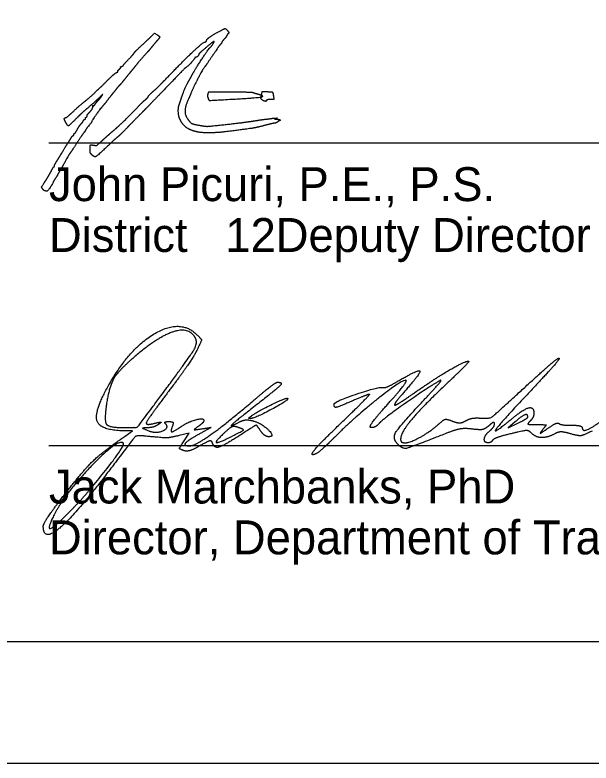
# Model space of a CAD drawing. Extents: x 0 to 96.2, y -27.5 to 31.3.
# Drawn here: x 69.212 to 71.59, y -0.113 to 2.975 of the extents above; entities that cross this region are included whole.
import ezdxf

# ---------------------------------------------------------------- set-up
doc = ezdxf.new("R2010")
doc.units = 0
for name, color, linetype in [('DIM', 7, 'Continuous'), ('TB1', 7, 'Continuous'), ('TB_SUPER_50x1', 7, 'Continuous'), ('text', 7, 'Continuous')]:
    doc.layers.add(name, color=color, linetype=linetype)

msp = doc.modelspace()

# ---------------------------------------------------------------- linework, layer by layer
at = {"layer": 'DIM'}
msp.add_lwpolyline([(43.2234, 21.3869), (74.7234, 21.3869), (74.7234, 0.3869), (43.2234, 0.3869)], close=True, dxfattribs=at)
at = {"layer": 'TB1'}
for p, q in [((69.352, 2.4468), (72.852, 2.4468)), ((69.352, 1.1985), (72.852, 1.1985))]:
    msp.add_line(p, q, dxfattribs=at)
at = {"layer": 'TB_SUPER_50x1'}
for p, q in [((70.0084, 2.6328), (70.0084, 2.6328)), ((70.2313, 2.6259), (70.2313, 2.6259)), ((69.5269, 2.4004), (69.5269, 2.4004)), ((69.336, 2.2489), (69.336, 2.2489)), ((69.8143, 1.4035), (69.8143, 1.4035)), ((70.1796, 1.3137), (70.1796, 1.3137)), ((71.3286, 1.3157), (71.3286, 1.3157)), ((70.1348, 1.272), (70.1348, 1.272)), ((70.5514, 1.2847), (70.5514, 1.2847))]:
    msp.add_line(p, q, dxfattribs=at)
for points in [[(69.7768, 2.8893), (69.7877, 2.9), (69.7973, 2.8942)], [(70.1011, 2.6567), (70.0105, 2.6572), (70.0078, 2.6492)], [(70.2529, 2.6574), (70.2311, 2.6579), (70.2282, 2.6442)], [(69.5708, 2.6419), (69.5742, 2.6483), (69.5678, 2.6419)], [(70.2666, 2.6275), (70.2814, 2.6275), (70.2797, 2.6406)], [(71.2768, 1.296), (71.2473, 1.2704), (71.288, 1.2901)], [(69.6666, 1.2366), (69.6973, 1.2578), (69.6595, 1.2585)], [(69.9096, 1.2167), (69.9308, 1.2491), (69.8891, 1.239)]]:
    msp.add_lwpolyline(points, dxfattribs=at)
for points in [[(70.0022, 2.8688), (70.0022, 2.874), (70.0282, 2.8932), (70.0543, 2.9072)], [(70.0543, 2.9072), (70.0769, 2.9192), (70.082, 2.9193), (70.0917, 2.9076)], [(70.0917, 2.9076), (70.0952, 2.9034), (70.095, 2.9016), (70.0906, 2.8968)], [(69.7353, 2.8501), (69.7522, 2.8659), (69.7709, 2.8835), (69.7768, 2.8893)], [(69.7973, 2.8942), (69.8089, 2.8874), (69.8095, 2.8814), (69.7997, 2.8707)], [(70.0758, 2.8761), (70.0705, 2.8705), (70.0662, 2.8647), (70.0662, 2.8633)], [(70.0854, 2.8887), (70.0854, 2.8874), (70.0811, 2.8818), (70.0758, 2.8761)], [(70.0906, 2.8968), (70.0877, 2.8936), (70.0854, 2.89), (70.0854, 2.8887)], [(69.7046, 2.8194), (69.7046, 2.8206), (69.7184, 2.8344), (69.7353, 2.8501)], [(69.7797, 2.8469), (69.7727, 2.8381), (69.7648, 2.8287), (69.7622, 2.8259)], [(69.7997, 2.8707), (69.7957, 2.8663), (69.7867, 2.8556), (69.7797, 2.8469)], [(69.8229, 2.699), (69.8932, 2.7726), (69.9852, 2.8608), (69.994, 2.863)], [(70.0342, 2.8657), (70.0342, 2.8679), (70.0091, 2.8485), (69.9857, 2.8281)], [(69.994, 2.863), (69.9985, 2.8641), (70.0022, 2.8667), (70.0022, 2.8688)], [(70.0167, 2.8403), (70.0213, 2.8444), (70.0342, 2.863), (70.0342, 2.8657)], [(70.0622, 2.8562), (70.0541, 2.8472), (70.0509, 2.8427), (70.0245, 2.8035)], [(70.0662, 2.8633), (70.0662, 2.8618), (70.0644, 2.8587), (70.0622, 2.8562)], [(69.6822, 2.7939), (69.6945, 2.8068), (69.7046, 2.8183), (69.7046, 2.8194)], [(69.7622, 2.8259), (69.7508, 2.8138), (69.72, 2.7784), (69.7093, 2.7651)], [(69.9429, 2.7278), (69.9548, 2.7501), (70.0102, 2.8346), (70.0167, 2.8403)], [(69.9702, 2.8121), (69.9702, 2.8083), (69.9616, 2.8003), (69.9576, 2.8003)], [(69.9857, 2.8281), (69.9772, 2.8207), (69.9702, 2.8135), (69.9702, 2.8121)], [(69.6598, 2.768), (69.6598, 2.7694), (69.6699, 2.781), (69.6822, 2.7939)], [(69.9541, 2.7979), (69.954, 2.795), (69.9209, 2.7587), (69.9184, 2.7587)], [(69.9576, 2.8003), (69.9557, 2.8003), (69.9541, 2.7992), (69.9541, 2.7979)], [(70.0245, 2.8035), (70.0096, 2.7815), (69.9968, 2.7628), (69.9958, 2.7619)], [(69.6361, 2.7419), (69.6351, 2.7429), (69.6378, 2.7469), (69.642, 2.7509)], [(69.642, 2.7509), (69.6463, 2.7548), (69.649, 2.7588), (69.6481, 2.7597)], [(69.6481, 2.7597), (69.6472, 2.7606), (69.6495, 2.7623), (69.6531, 2.7634)], [(69.6531, 2.7634), (69.6568, 2.7646), (69.6598, 2.7667), (69.6598, 2.768)], [(69.7093, 2.7651), (69.7028, 2.7572), (69.6929, 2.745), (69.6871, 2.7379)], [(69.9184, 2.7587), (69.9164, 2.7587), (69.8857, 2.7276), (69.816, 2.6549)], [(69.9958, 2.7619), (69.989, 2.7554), (69.9494, 2.6795), (69.9366, 2.6483)], [(69.5949, 2.7066), (69.6114, 2.7228), (69.6279, 2.7369), (69.6314, 2.7381)], [(69.6314, 2.7381), (69.635, 2.7392), (69.637, 2.7409), (69.6361, 2.7419)], [(69.6871, 2.7379), (69.6814, 2.7309), (69.6697, 2.7165), (69.6612, 2.7059)], [(69.9283, 2.7011), (69.9299, 2.7038), (69.9365, 2.7158), (69.9429, 2.7278)], [(69.5023, 2.6204), (69.5197, 2.6346), (69.5537, 2.6662), (69.5949, 2.7066)], [(69.6612, 2.7059), (69.6527, 2.6954), (69.6441, 2.6853), (69.6421, 2.6835)], [(69.7821, 2.6596), (69.793, 2.6692), (69.8114, 2.687), (69.8229, 2.699)], [(69.8982, 2.6307), (69.9031, 2.6471), (69.9216, 2.6901), (69.9283, 2.7011)], [(69.6259, 2.6643), (69.619, 2.6555), (69.6126, 2.6476), (69.6116, 2.6467)], [(69.6421, 2.6835), (69.6401, 2.6818), (69.6328, 2.6731), (69.6259, 2.6643)], [(69.7622, 2.6387), (69.7622, 2.6405), (69.7711, 2.6499), (69.7821, 2.6596)], [(70.1954, 2.6539), (70.1934, 2.6551), (70.151, 2.6564), (70.1011, 2.6567)], [(70.2763, 2.6553), (70.2754, 2.6562), (70.2649, 2.6571), (70.2529, 2.6574)], [(69.5678, 2.6419), (69.556, 2.63), (69.5335, 2.6096), (69.5094, 2.5891)], [(69.5431, 2.6075), (69.5463, 2.6124), (69.553, 2.6206), (69.5582, 2.6259)], [(69.5582, 2.6259), (69.5633, 2.6312), (69.569, 2.6384), (69.5708, 2.6419)], [(69.5948, 2.6253), (69.5865, 2.6144), (69.5778, 2.6036), (69.5755, 2.6013)], [(69.6116, 2.6467), (69.6107, 2.6458), (69.6031, 2.6362), (69.5948, 2.6253)], [(69.7209, 2.5975), (69.7307, 2.6079), (69.7441, 2.6206), (69.7505, 2.6259)], [(69.816, 2.6549), (69.7908, 2.6286), (69.7551, 2.5917), (69.7366, 2.573)], [(69.7505, 2.6259), (69.7569, 2.6312), (69.7622, 2.6369), (69.7622, 2.6387)], [(69.8899, 2.6058), (69.8915, 2.6098), (69.8953, 2.621), (69.8982, 2.6307)], [(69.9284, 2.6291), (69.9155, 2.6016), (69.9123, 2.5656), (69.9213, 2.5514)], [(69.9366, 2.6483), (69.9337, 2.6413), (69.93, 2.6326), (69.9284, 2.6291)], [(70.0078, 2.6492), (70.0063, 2.6446), (70.0065, 2.6377), (70.0084, 2.6328)], [(70.0084, 2.6328), (70.0122, 2.6227), (70.0153, 2.6225), (70.1078, 2.6275)], [(70.1078, 2.6275), (70.2094, 2.633), (70.2463, 2.6403), (70.2125, 2.6483)], [(70.2125, 2.6483), (70.2051, 2.6501), (70.1974, 2.6526), (70.1954, 2.6539)], [(70.2282, 2.6442), (70.2256, 2.6324), (70.2261, 2.6299), (70.2313, 2.6259)], [(70.2313, 2.6259), (70.2383, 2.6206), (70.2518, 2.6196), (70.2518, 2.6243)], [(70.2518, 2.6243), (70.2518, 2.6261), (70.2584, 2.6275), (70.2666, 2.6275)], [(70.2797, 2.6406), (70.2787, 2.6478), (70.2772, 2.6544), (70.2763, 2.6553)], [(69.4493, 2.574), (69.4706, 2.5942), (69.4762, 2.5991), (69.5023, 2.6204)], [(69.5135, 2.5673), (69.5251, 2.5792), (69.5353, 2.5956), (69.5332, 2.5991)], [(69.5755, 2.6013), (69.5688, 2.5946), (69.5286, 2.5382), (69.5286, 2.5355)], [(69.5332, 2.5991), (69.5317, 2.6014), (69.5321, 2.6021), (69.5341, 2.6008)], [(69.5341, 2.6008), (69.536, 2.5997), (69.54, 2.6027), (69.5431, 2.6075)], [(69.6366, 2.5139), (69.6493, 2.525), (69.6949, 2.5703), (69.7209, 2.5975)], [(69.8917, 2.5471), (69.8864, 2.5591), (69.8854, 2.5944), (69.8899, 2.6058)], [(69.4224, 2.5521), (69.4256, 2.5532), (69.4377, 2.563), (69.4493, 2.574)], [(69.5094, 2.5891), (69.4962, 2.5779), (69.4773, 2.5606), (69.4675, 2.5507)], [(69.5094, 2.5585), (69.5094, 2.561), (69.5112, 2.565), (69.5135, 2.5673)], [(69.7366, 2.573), (69.7181, 2.5543), (69.6897, 2.5253), (69.6734, 2.5085)], [(69.4215, 2.5314), (69.415, 2.5438), (69.4153, 2.5499), (69.4224, 2.5521)], [(69.4675, 2.5507), (69.4364, 2.5193), (69.4293, 2.5163), (69.4215, 2.5314)], [(69.4848, 2.5258), (69.489, 2.5303), (69.4933, 2.5363), (69.4944, 2.5392)], [(69.4944, 2.5392), (69.4955, 2.542), (69.4979, 2.5443), (69.4997, 2.5443)], [(69.4997, 2.5443), (69.5015, 2.5443), (69.503, 2.5465), (69.503, 2.5491)], [(69.503, 2.5491), (69.503, 2.5518), (69.5044, 2.5539), (69.5062, 2.5539)], [(69.5062, 2.5539), (69.5079, 2.5539), (69.5094, 2.556), (69.5094, 2.5585)], [(69.5286, 2.5355), (69.5286, 2.5335), (69.5252, 2.5289), (69.5099, 2.5105)], [(69.954, 2.495), (69.9283, 2.5026), (69.9012, 2.5252), (69.8917, 2.5471)], [(69.9213, 2.5514), (69.9341, 2.5314), (69.9474, 2.524), (69.98, 2.5186)], [(70.0678, 2.5216), (70.1238, 2.5278), (70.1738, 2.5341), (70.2054, 2.5391)], [(70.2054, 2.5391), (70.2182, 2.5412), (70.2482, 2.5452), (70.2582, 2.5462)], [(70.2582, 2.5462), (70.2626, 2.5466), (70.2662, 2.5472), (70.2662, 2.5475)], [(70.2662, 2.5475), (70.2662, 2.5478), (70.2734, 2.5486), (70.2822, 2.5492)], [(70.2822, 2.5492), (70.2939, 2.5501), (70.296, 2.5496), (70.2902, 2.5477)], [(70.2945, 2.5331), (70.2919, 2.5305), (70.2866, 2.5283), (70.2827, 2.5282)], [(70.2902, 2.5477), (70.2829, 2.5452), (70.2833, 2.5449), (70.2942, 2.5446)], [(70.2942, 2.5446), (70.3008, 2.5445), (70.3062, 2.5429), (70.3062, 2.5411)], [(70.3027, 2.5379), (70.3009, 2.5379), (70.2972, 2.5358), (70.2945, 2.5331)], [(70.3062, 2.5411), (70.3062, 2.5394), (70.3046, 2.5379), (70.3027, 2.5379)], [(69.4577, 2.4867), (69.4591, 2.4867), (69.4641, 2.4936), (69.4687, 2.5021)], [(69.4687, 2.5021), (69.4733, 2.5106), (69.4806, 2.5212), (69.4848, 2.5258)], [(69.5099, 2.5105), (69.5083, 2.5086), (69.5052, 2.5036), (69.5029, 2.4993)], [(69.6067, 2.4879), (69.6171, 2.4969), (69.6306, 2.5086), (69.6366, 2.5139)], [(69.6734, 2.5085), (69.6572, 2.4917), (69.6394, 2.4745), (69.6341, 2.4703)], [(69.98, 2.5186), (70.0007, 2.5152), (70.0121, 2.5156), (70.0678, 2.5216)], [(70.2518, 2.5216), (70.2141, 2.5113), (70.1749, 2.5048), (70.0806, 2.4931)], [(70.2827, 2.5282), (70.2789, 2.5282), (70.265, 2.5252), (70.2518, 2.5216)], [(69.4447, 2.4696), (69.447, 2.4737), (69.4503, 2.4771), (69.4519, 2.4771)], [(69.4519, 2.4771), (69.4536, 2.4771), (69.455, 2.4793), (69.455, 2.4819)], [(69.455, 2.4819), (69.455, 2.4846), (69.4562, 2.4867), (69.4577, 2.4867)], [(69.4967, 2.4899), (69.4955, 2.489), (69.4827, 2.4703), (69.4683, 2.4483)], [(69.5029, 2.4993), (69.5007, 2.495), (69.4979, 2.4908), (69.4967, 2.4899)], [(69.5686, 2.4536), (69.5791, 2.4634), (69.5963, 2.4789), (69.6067, 2.4879)], [(70.0806, 2.4931), (70.0398, 2.4881), (69.9742, 2.4891), (69.954, 2.495)], [(69.4003, 2.3974), (69.4174, 2.4261), (69.4251, 2.4386), (69.4323, 2.4496)], [(69.4323, 2.4496), (69.4369, 2.4564), (69.4425, 2.4654), (69.4447, 2.4696)], [(69.4683, 2.4483), (69.4538, 2.4263), (69.4408, 2.4068), (69.4393, 2.4049)], [(69.6012, 2.4406), (69.5536, 2.3948), (69.5391, 2.3869), (69.5269, 2.4004)], [(69.5378, 2.4376), (69.5485, 2.4358), (69.5509, 2.4371), (69.5686, 2.4536)], [(69.6341, 2.4703), (69.6287, 2.4661), (69.6139, 2.4528), (69.6012, 2.4406)], [(69.5269, 2.4004), (69.5231, 2.4046), (69.5213, 2.4111), (69.5216, 2.4198)], [(69.5216, 2.4198), (69.5223, 2.4376), (69.5243, 2.4397), (69.5378, 2.4376)], [(69.3854, 2.3735), (69.3911, 2.3824), (69.3978, 2.3932), (69.4003, 2.3974)], [(69.4393, 2.4049), (69.4368, 2.4018), (69.4326, 2.3944), (69.4113, 2.3563)], [(69.36, 2.3283), (69.3654, 2.3389), (69.371, 2.348), (69.3724, 2.3486)], [(69.3724, 2.3486), (69.3738, 2.3492), (69.375, 2.3514), (69.375, 2.3535)], [(69.375, 2.3535), (69.375, 2.3556), (69.3797, 2.3646), (69.3854, 2.3735)], [(69.4113, 2.3563), (69.4066, 2.348), (69.3994, 2.3357), (69.3953, 2.3292)], [(69.3355, 2.2871), (69.3435, 2.2992), (69.3545, 2.3178), (69.36, 2.3283)], [(69.3953, 2.3292), (69.3911, 2.3226), (69.3878, 2.3166), (69.3878, 2.3157)], [(69.3258, 2.2576), (69.3213, 2.2646), (69.3219, 2.2663), (69.3355, 2.2871)], [(69.3782, 2.3), (69.3729, 2.2922), (69.3686, 2.2847), (69.3686, 2.2833)], [(69.3878, 2.3157), (69.3878, 2.3149), (69.3835, 2.3078), (69.3782, 2.3)], [(69.336, 2.2489), (69.3331, 2.2497), (69.3285, 2.2536), (69.3258, 2.2576)], [(69.3686, 2.2833), (69.3686, 2.2797), (69.3455, 2.2467), (69.3432, 2.2471)], [(69.3432, 2.2471), (69.3422, 2.2473), (69.339, 2.2481), (69.336, 2.2489)], [(69.603, 1.4543), (69.6892, 1.6047), (69.8973, 1.7207), (69.963, 1.655)], [(69.9541, 1.6459), (69.9281, 1.6879), (69.802, 1.6467), (69.7066, 1.5651)], [(69.8143, 1.4035), (69.9356, 1.567), (69.9681, 1.6232), (69.9541, 1.6459)], [(69.963, 1.655), (69.9818, 1.6363), (69.9818, 1.6312), (69.9635, 1.5928)], [(69.9635, 1.5928), (69.9525, 1.5698), (69.9008, 1.4943), (69.8486, 1.4249)], [(69.7066, 1.5651), (69.64, 1.5081), (69.6012, 1.4439), (69.5901, 1.3727)], [(70.8567, 1.4128), (70.9372, 1.4694), (71.0686, 1.5466), (71.0843, 1.5466)], [(71.0843, 1.5466), (71.0892, 1.5466), (71.0478, 1.504), (70.9925, 1.4519)], [(71.311, 1.4332), (71.386, 1.5023), (71.452, 1.5589), (71.4577, 1.559)], [(71.4577, 1.559), (71.4635, 1.5591), (71.4114, 1.4989), (71.3421, 1.4253)], [(70.7977, 1.4663), (70.8765, 1.5124), (70.8887, 1.4992), (70.8295, 1.4319)], [(69.6595, 1.2585), (69.5616, 1.2602), (69.5382, 1.3413), (69.603, 1.4543)], [(70.1931, 1.3808), (70.2436, 1.4237), (70.289, 1.4588), (70.2942, 1.4589)], [(70.2942, 1.4589), (70.3191, 1.4594), (70.2957, 1.4339), (70.2098, 1.3666)], [(70.8258, 1.466), (70.8162, 1.4757), (70.6065, 1.3087), (70.5286, 1.2294)], [(70.9661, 1.4656), (70.917, 1.4378), (70.7287, 1.3056), (70.7155, 1.2896)], [(70.7321, 1.4371), (70.7377, 1.4352), (70.7672, 1.4484), (70.7977, 1.4663)], [(70.748, 1.3657), (70.7943, 1.4174), (70.8293, 1.4626), (70.8258, 1.466)], [(70.9925, 1.4519), (70.8928, 1.3582), (70.8036, 1.25), (70.8036, 1.2231)], [(70.9009, 1.3867), (70.9471, 1.4359), (70.9764, 1.4714), (70.9661, 1.4656)], [(69.8486, 1.4249), (69.7963, 1.3555), (69.7536, 1.2949), (69.7536, 1.2901)], [(70.5288, 1.3685), (70.529, 1.379), (70.7164, 1.4422), (70.7321, 1.4371)], [(70.8295, 1.4319), (70.8015, 1.4001), (70.7786, 1.3704), (70.7786, 1.366)], [(71.136, 1.3108), (71.1695, 1.308), (71.1929, 1.3244), (71.311, 1.4332)], [(71.3421, 1.4253), (71.2126, 1.2878), (71.1805, 1.2405), (71.2627, 1.3082)], [(69.6681, 1.2716), (69.7148, 1.2716), (69.7194, 1.2757), (69.8143, 1.4035)], [(70.1796, 1.3137), (70.2, 1.3315), (70.3321, 1.3973), (70.3372, 1.3922)], [(70.3372, 1.3922), (70.3434, 1.386), (70.2008, 1.3091), (70.1831, 1.3091)], [(70.5514, 1.2847), (70.6225, 1.3531), (70.6778, 1.4091), (70.6744, 1.4091)], [(70.6744, 1.4091), (70.6709, 1.4091), (70.6419, 1.3979), (70.6098, 1.3841)], [(70.7786, 1.366), (70.7786, 1.3615), (70.8137, 1.3826), (70.8567, 1.4128)], [(69.5901, 1.3727), (69.5787, 1.2993), (69.6001, 1.2716), (69.6681, 1.2716)], [(69.9317, 1.1966), (69.9548, 1.1966), (70.0808, 1.2854), (70.1931, 1.3808)], [(70.2098, 1.3666), (70.1166, 1.2936), (70.0952, 1.272), (70.1391, 1.2955)], [(70.6098, 1.3841), (70.5472, 1.3573), (70.5285, 1.3537), (70.5288, 1.3685)], [(70.6822, 1.2716), (70.6719, 1.2716), (70.7008, 1.3129), (70.748, 1.3657)], [(70.7938, 1.201), (70.7686, 1.2262), (70.7975, 1.2763), (70.9009, 1.3867)], [(71.5536, 1.2701), (71.5536, 1.2473), (71.6489, 1.3087), (71.7192, 1.3769)], [(71.2627, 1.3082), (71.3111, 1.3481), (71.3536, 1.3585), (71.3536, 1.3304)], [(71.3536, 1.3304), (71.3536, 1.3214), (71.3468, 1.3074), (71.3386, 1.2991)], [(69.8977, 1.276), (69.9266, 1.2958), (69.9911, 1.3133), (69.9911, 1.3014)], [(69.9911, 1.3014), (69.9911, 1.2968), (69.9813, 1.286), (69.9694, 1.2773)], [(70.1391, 1.2955), (70.1517, 1.3023), (70.1756, 1.3044), (70.1922, 1.3002)], [(70.1831, 1.3091), (70.1783, 1.3091), (70.1768, 1.3112), (70.1796, 1.3137)], [(70.1922, 1.3002), (70.2283, 1.2911), (70.2867, 1.2341), (70.2599, 1.2341)], [(70.9611, 1.2866), (70.9814, 1.3047), (70.9943, 1.3073), (71.018, 1.2983)], [(71.018, 1.2983), (71.0382, 1.2906), (71.057, 1.2913), (71.073, 1.3003)], [(71.073, 1.3003), (71.0864, 1.3079), (71.1147, 1.3126), (71.136, 1.3108)], [(71.3286, 1.3157), (71.3286, 1.3292), (71.3045, 1.32), (71.2768, 1.296)], [(71.288, 1.2901), (71.3103, 1.3009), (71.3286, 1.3124), (71.3286, 1.3157)], [(71.3386, 1.2991), (71.3269, 1.2875), (71.3328, 1.2841), (71.3651, 1.2841)], [(69.7598, 1.271), (69.7374, 1.2701), (69.7379, 1.2688), (69.764, 1.2584)], [(69.7536, 1.2901), (69.7536, 1.2853), (69.769, 1.285), (69.788, 1.2894)], [(69.8036, 1.2847), (69.7933, 1.2777), (69.7736, 1.2716), (69.7598, 1.271)], [(69.764, 1.2584), (69.7939, 1.2464), (69.8501, 1.2709), (69.8327, 1.2884)], [(69.788, 1.2894), (69.8135, 1.2953), (69.8175, 1.2941), (69.8036, 1.2847)], [(69.8327, 1.2884), (69.8281, 1.2929), (69.8344, 1.2966), (69.8466, 1.2966)], [(69.8466, 1.2966), (69.8612, 1.2966), (69.8663, 1.2902), (69.8616, 1.2779)], [(69.8616, 1.2779), (69.8526, 1.2546), (69.8655, 1.254), (69.8977, 1.276)], [(69.9694, 1.2773), (69.9505, 1.2635), (69.9525, 1.2622), (69.9851, 1.2671)], [(69.9851, 1.2671), (70.0218, 1.2727), (70.0217, 1.2724), (69.9763, 1.2473)], [(70.1348, 1.272), (70.1176, 1.2784), (70.1011, 1.2732), (70.0817, 1.2555)], [(70.1067, 1.2357), (70.1531, 1.2594), (70.1567, 1.264), (70.1348, 1.272)], [(70.2252, 1.2588), (70.2084, 1.2829), (70.2063, 1.2824), (70.1406, 1.24)], [(70.4411, 1.1598), (70.4308, 1.16), (70.4804, 1.2162), (70.5514, 1.2847)], [(70.7155, 1.2896), (70.7072, 1.2797), (70.6923, 1.2716), (70.6822, 1.2716)], [(70.8216, 1.2091), (70.8433, 1.2091), (70.9247, 1.2543), (70.9611, 1.2866)], [(71.099, 1.2657), (71.0698, 1.2694), (71.0299, 1.2629), (70.9934, 1.2485)], [(71.1685, 1.2801), (71.1528, 1.2659), (71.1316, 1.2615), (71.099, 1.2657)], [(71.1911, 1.2876), (71.1911, 1.2947), (71.1809, 1.2913), (71.1685, 1.2801)], [(71.1723, 1.2591), (71.1826, 1.2677), (71.1911, 1.2805), (71.1911, 1.2876)], [(71.3651, 1.2841), (71.4027, 1.2841), (71.405, 1.2821), (71.3895, 1.2627)], [(71.3895, 1.2627), (71.3775, 1.2477), (71.384, 1.2495), (71.4112, 1.2686)], [(71.4112, 1.2686), (71.4326, 1.2836), (71.4534, 1.2927), (71.4573, 1.2888)], [(71.4573, 1.2888), (71.4612, 1.2848), (71.4845, 1.2816), (71.509, 1.2816)], [(71.509, 1.2816), (71.5335, 1.2816), (71.5536, 1.2765), (71.5536, 1.2701)], [(69.4157, 0.9944), (69.4933, 1.0949), (69.5734, 1.1722), (69.6666, 1.2366)], [(69.7479, 1.2367), (69.7144, 1.24), (69.7027, 1.2295), (69.6261, 1.1279)], [(69.8891, 1.239), (69.8487, 1.2293), (69.8264, 1.2289), (69.7479, 1.2367)], [(69.9763, 1.2473), (69.9252, 1.2191), (69.9055, 1.1966), (69.9317, 1.1966)], [(70.1406, 1.24), (70.0717, 1.1957), (70.0342, 1.1859), (70.0261, 1.2103)], [(70.0817, 1.2555), (70.0375, 1.215), (70.0487, 1.2061), (70.1067, 1.2357)], [(70.2599, 1.2341), (70.2503, 1.2341), (70.2347, 1.2452), (70.2252, 1.2588)], [(70.9934, 1.2485), (70.8474, 1.1908), (70.8123, 1.1825), (70.7938, 1.201)], [(71.1653, 1.2091), (71.147, 1.2091), (71.1515, 1.2419), (71.1723, 1.2591)], [(71.2597, 1.2466), (71.2213, 1.2374), (71.187, 1.2252), (71.1835, 1.2195)], [(71.344, 1.2487), (71.3329, 1.2598), (71.3128, 1.2593), (71.2597, 1.2466)], [(71.4403, 1.2462), (71.4096, 1.2298), (71.3617, 1.231), (71.344, 1.2487)], [(71.5048, 1.2463), (71.4779, 1.254), (71.4548, 1.254), (71.4403, 1.2462)], [(71.5939, 1.2576), (71.5565, 1.2391), (71.5379, 1.2368), (71.5048, 1.2463)], [(69.6595, 1.2074), (69.6386, 1.2283), (69.4201, 1.0026), (69.3738, 0.9123)], [(69.4439, 0.931), (69.5115, 1.0001), (69.6672, 1.1997), (69.6595, 1.2074)], [(69.9084, 1.1767), (69.8902, 1.1837), (69.8903, 1.1873), (69.9096, 1.2167)], [(70.0261, 1.2103), (70.0233, 1.2189), (70.004, 1.2137), (69.975, 1.1965)], [(70.5286, 1.2294), (70.4908, 1.191), (70.4514, 1.1596), (70.4411, 1.1598)], [(70.8036, 1.2231), (70.8036, 1.2154), (70.8117, 1.2091), (70.8216, 1.2091)], [(71.1835, 1.2195), (71.18, 1.2138), (71.1718, 1.2091), (71.1653, 1.2091)], [(69.975, 1.1965), (69.9493, 1.1814), (69.9194, 1.1725), (69.9084, 1.1767)], [(69.6261, 1.1279), (69.4737, 0.9258), (69.3286, 0.7971), (69.3286, 0.8641)], [(69.3286, 0.8641), (69.3286, 0.8738), (69.3678, 0.9324), (69.4157, 0.9944)], [(69.3738, 0.9123), (69.3425, 0.8513), (69.3742, 0.8598), (69.4439, 0.931)]]:
    msp.add_open_spline(points, degree=2, dxfattribs=at)
at = {"layer": 'text'}
msp.add_lwpolyline([(41.2234, -0.1131), (75.2234, -0.1131), (75.2234, 21.8869), (41.2234, 21.8869)], close=True, dxfattribs=at)

# ---------------------------------------------------------------- texts
at = {"layer": 'TB_SUPER_50x1'}
for s, p in [('John Picuri, P.E., P.S.', (69.352, 2.2068)), ('District       Deputy Director', (69.352, 1.9968)), ('              12', (69.352, 1.9968)), ('Jack Marchbanks, PhD', (69.352, 0.9585)), ('Director, Department of Transportation', (69.352, 0.7485))]:
    msp.add_text(s, height=0.14, dxfattribs=at).set_placement(p)

doc.saveas('drawing.dxf')
